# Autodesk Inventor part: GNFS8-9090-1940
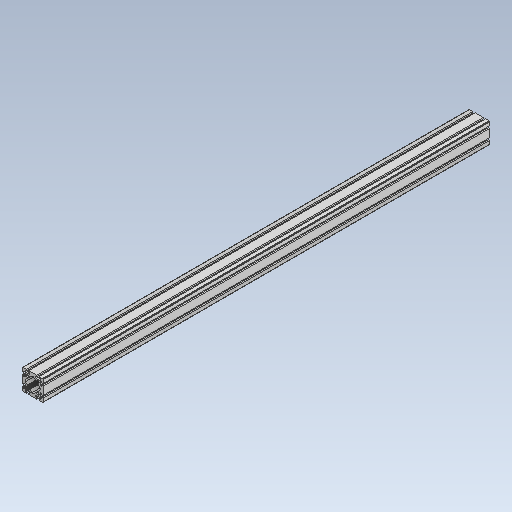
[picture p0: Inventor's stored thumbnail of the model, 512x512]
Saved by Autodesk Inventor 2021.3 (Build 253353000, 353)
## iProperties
Created: 2022-02
Part Number: GNFS8-9090-1940
Material: 一般
Document SubType Name: Modeling
Designer: kengo
Density: 1 g/cm^3
Appearance: 既定
Author: kengo
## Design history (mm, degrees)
feature "GNFS8-9090-1940"
node "ソリッド1"
